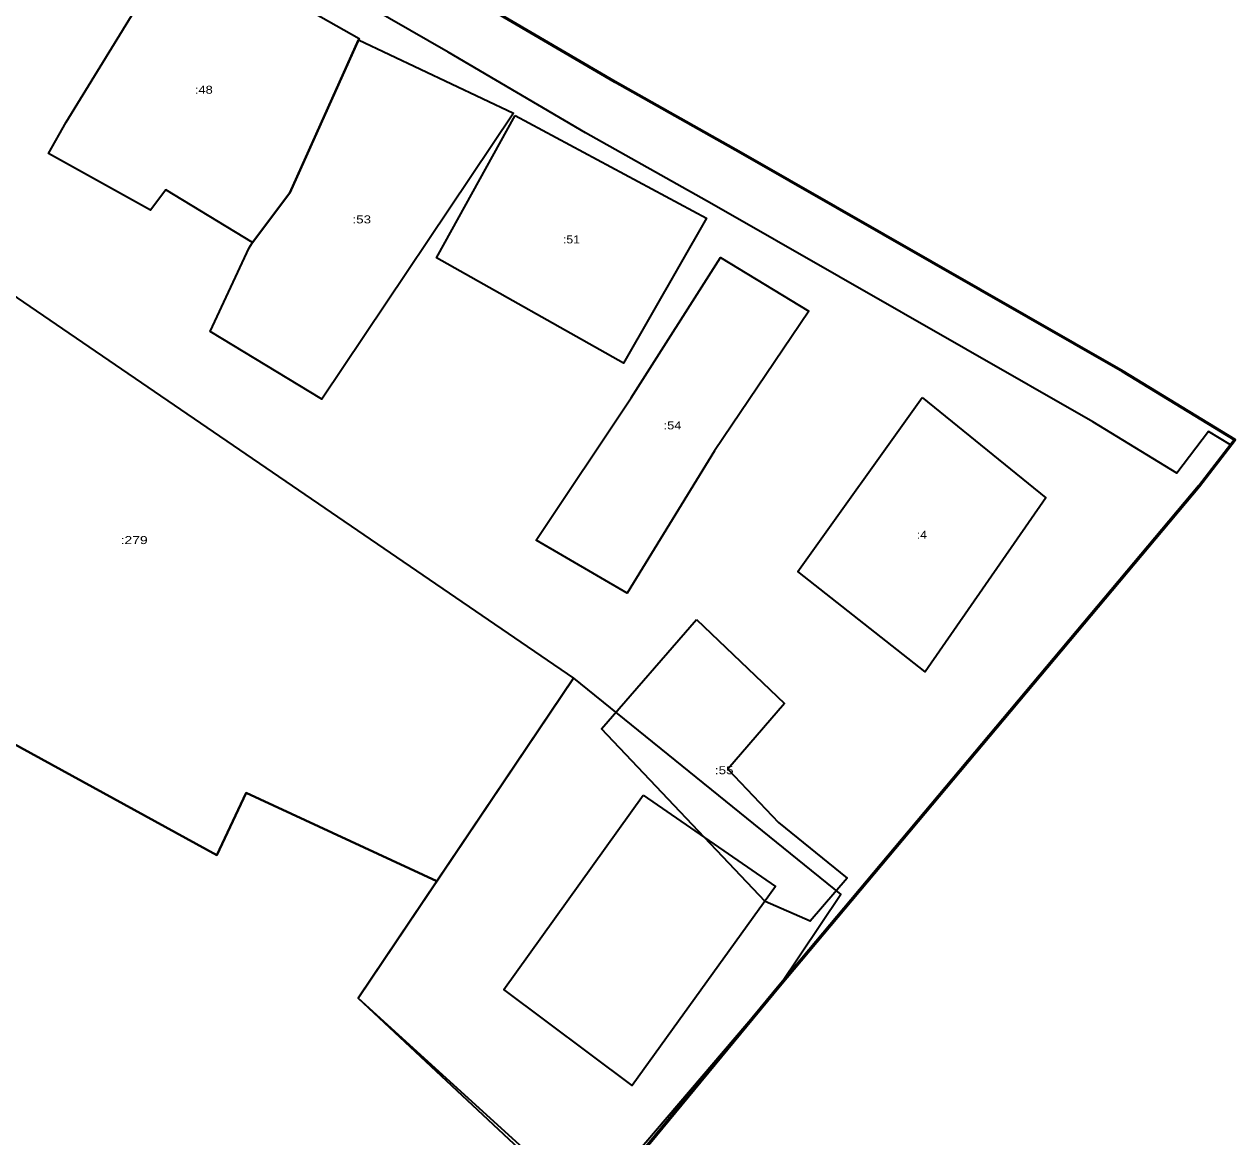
# Model space of a CAD drawing. Extents: x 1178597 to 1179642, y 361068 to 362800.
# Drawn here: x 1179414.8 to 1179641.7, y 362195.6 to 362404.2 of the extents above; entities that cross this region are included whole.
import ezdxf
from ezdxf.enums import TextEntityAlignment as Align

# ---------------------------------------------------------------- set-up
doc = ezdxf.new("R2010")
doc.units = 0
doc.header["$LTSCALE"] = 0.6
doc.layers.add('2', color=7, linetype='Continuous', lineweight=35)
doc.layers.add('4', color=7, linetype='Continuous', lineweight=53)

msp = doc.modelspace()

# ---------------------------------------------------------------- linework, layer by layer
at = {"layer": '2'}
msp.add_lwpolyline([(1179126.54, 362623.96), (1179252.11, 362551.57), (1179286.27, 362531.76), (1179441.83, 362441.77), (1179499.74, 362408.44), (1179525.44, 362393.35), (1179549.05, 362380.04), (1179620.68, 362339.09), (1179641.66, 362326.26), (1179640.88, 362325.28), (1179636.71, 362327.82), (1179630.82, 362320), (1179615.08, 362329.62), (1179543.62, 362370.48), (1179519.96, 362383.81), (1179494.22, 362398.93), (1179436.33, 362432.25), (1179280.76, 362522.24), (1179246.62, 362542.08), (1179121.07, 362614.45)], dxfattribs=at)
for points in [[(1179443.93, 362420.54), (1179477.56, 362401.53), (1179464.51, 362372.54), (1179457.54, 362363.24), (1179441.32, 362373.15), (1179438.43, 362369.32), (1179419.28, 362379.91), (1179422.59, 362385.8)], [(1179477.43, 362401.26), (1179506.44, 362387.53), (1179470.55, 362333.9), (1179449.61, 362346.54), (1179456.9, 362362.24), (1179457.54, 362363.24), (1179464.51, 362372.54)], [(1179506.77, 362387.05), (1179542.62, 362367.83), (1179527.09, 362340.61), (1179492.03, 362360.4)], [(1179299.94, 362382.52), (1179342.38, 362357.65), (1179346.64, 362363.23), (1179360.06, 362355.65), (1179352.99, 362340.53), (1179379.32, 362326.13), (1179364.89, 362295.49), (1179450.87, 362248.4), (1179456.38, 362260.05), (1179492.1, 362243.51), (1179477.34, 362221.57), (1179513.35, 362187.89), (1179514.65, 362186.48), (1179490.95, 362151.84), (1179425.31, 362184.2), (1179392.38, 362201.34), (1179405.38, 362229.11), (1179263.24, 362305.15)], [(1179375.31, 362366.1), (1179386.33, 362371.39), (1179517.72, 362281.58), (1179492.1, 362243.51), (1179456.38, 362260.05), (1179450.87, 362248.4), (1179364.89, 362295.49), (1179379.32, 362326.13), (1179352.99, 362340.53), (1179360.06, 362355.65), (1179366.93, 362351.77)], [(1179528.53, 362334.14), (1179545.27, 362360.43), (1179561.82, 362350.37), (1179544.12, 362324.18), (1179527.76, 362297.49), (1179510.72, 362307.44)], [(1179583.04, 362334.17), (1179606.27, 362315.4), (1179583.61, 362282.75), (1179559.76, 362301.59)], [(1179540.76, 362292.57), (1179557.27, 362276.8), (1179546.61, 362264.5), (1179556.12, 362254.52), (1179568.98, 362244.05), (1179562.09, 362236.02), (1179553.64, 362239.71), (1179522.95, 362272.05)], [(1179517.72, 362281.58), (1179567.81, 362241.02), (1179556.38, 362223.96), (1179520.72, 362182.12), (1179477.34, 362221.57)], [(1179530.76, 362259.6), (1179555.6, 362242.47), (1179528.68, 362205.2), (1179504.66, 362223.16)]]:
    msp.add_lwpolyline(points, close=True, dxfattribs=at)
at = {"layer": '4'}
msp.add_lwpolyline([(1179518.35, 362177.86), (1179556.38, 362223.96), (1179634.96, 362317.55), (1179641.66, 362326.26), (1179620.68, 362339.09), (1179549.05, 362380.04), (1179525.44, 362393.35), (1179499.74, 362408.44), (1179441.83, 362441.77), (1179286.27, 362531.76), (1179252.11, 362551.57), (1179099.35, 362639.55)], dxfattribs=at)

# ---------------------------------------------------------------- texts
at = {"layer": '2'}
for s, width, p in [(':48', 1.2, (1179448.42, 362391.14)), (':53', 1.25, (1179478.025, 362366.83)), (':51', 1.15, (1179517.325, 362363.08)), (':54', 1.2, (1179536.269, 362328.21)), (':279', 1.3, (1179435.356, 362306.7)), (':4', 1.15, (1179583.015, 362307.71)), (':55', 1.25, (1179545.965, 362263.545))]:
    msp.add_text(s, height=1.5, dxfattribs=dict(at, width=width)).set_placement(p, align=Align.CENTER)

doc.saveas('drawing.dxf')
